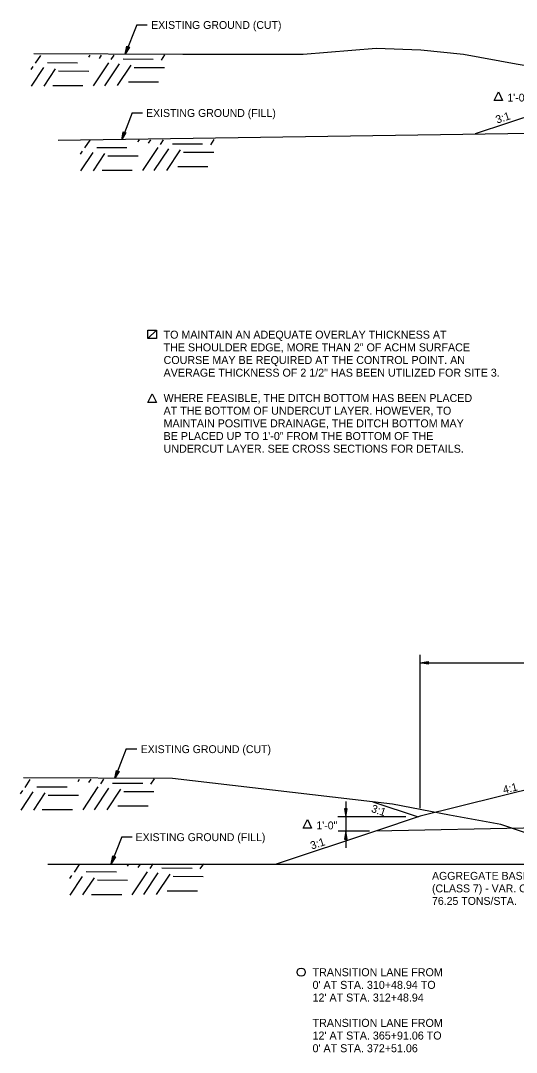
# Model space of a CAD drawing. Extents: x 1398565 to 1398920, y 1968324 to 1968581.
# Drawn here: x 1398764 to 1398801.2, y 1968479.9 to 1968557.3 of the extents above; entities that cross this region are included whole.
import ezdxf

# ---------------------------------------------------------------- set-up
doc = ezdxf.new("R2010")
doc.units = 0
for name, color, linetype in [('10', 7, 'Continuous'), ('19', 7, 'Continuous'), ('42', 7, 'Continuous'), ('9', 7, 'Continuous'), ('Default', 7, 'Continuous')]:
    doc.layers.add(name, color=color, linetype=linetype)

msp = doc.modelspace()

# ---------------------------------------------------------------- linework, layer by layer
at = {"layer": '10'}
for points in [[(1398799.825, 1968551.931), (1398800.145, 1968551.29), (1398799.504, 1968551.29)], [(1398773.545, 1968534.07), (1398774.186, 1968534.07), (1398774.186, 1968533.428), (1398773.545, 1968533.428)], [(1398773.545, 1968534.07), (1398774.186, 1968534.07), (1398773.545, 1968533.428)], [(1398773.865, 1968529.292), (1398774.186, 1968528.65), (1398773.545, 1968528.65)], [(1398785.503, 1968497.368), (1398785.823, 1968496.727), (1398785.182, 1968496.727)]]:
    msp.add_lwpolyline(points, close=True, dxfattribs=at)
msp.add_circle((1398785.033, 1968485.929), 0.306, dxfattribs=at)
at = {"layer": '19'}
for p, q in [((1398772.703, 1968556.959), (1398771.847, 1968554.758)), ((1398772.703, 1968556.959), (1398773.486, 1968556.959)), ((1398771.847, 1968554.758), (1398771.966, 1968555.355)), ((1398772.162, 1968555.279), (1398771.847, 1968554.758)), ((1398771.891, 1968554.912), (1398772.018, 1968555.335)), ((1398772.115, 1968555.297), (1398771.919, 1968554.901)), ((1398771.966, 1968555.355), (1398772.162, 1968555.279)), ((1398806.753, 1968551.672), (1398798.077, 1968548.78)), ((1398772.364, 1968550.361), (1398771.578, 1968548.342)), ((1398772.364, 1968550.361), (1398773.146, 1968550.361)), ((1398771.578, 1968548.342), (1398771.698, 1968548.939)), ((1398771.893, 1968548.863), (1398771.578, 1968548.342)), ((1398771.622, 1968548.496), (1398771.749, 1968548.919)), ((1398771.847, 1968548.881), (1398771.65, 1968548.485)), ((1398771.698, 1968548.939), (1398771.893, 1968548.863)), ((1398793.969, 1968498.237), (1398793.969, 1968509.724)), ((1398793.969, 1968509.124), (1398794.569, 1968509.229)), ((1398793.969, 1968509.124), (1398817.969, 1968509.124)), ((1398794.569, 1968509.019), (1398793.969, 1968509.124)), ((1398794.129, 1968509.139), (1398794.569, 1968509.174)), ((1398794.569, 1968509.069), (1398794.129, 1968509.109)), ((1398794.569, 1968509.229), (1398794.569, 1968509.019)), ((1398771.919, 1968502.667), (1398771.063, 1968500.465)), ((1398771.919, 1968502.667), (1398772.702, 1968502.667)), ((1398771.063, 1968500.465), (1398771.183, 1968501.062)), ((1398771.378, 1968500.986), (1398771.063, 1968500.465)), ((1398771.107, 1968500.62), (1398771.234, 1968501.042)), ((1398771.332, 1968501.004), (1398771.135, 1968500.609)), ((1398771.183, 1968501.062), (1398771.378, 1968500.986)), ((1398809.969, 1968501.621), (1398793.969, 1968497.621)), ((1398788.392, 1968498.729), (1398788.392, 1968497.454)), ((1398790.404, 1968498.711), (1398793.821, 1968497.572)), ((1398788.497, 1968498.172), (1398788.287, 1968498.172)), ((1398788.287, 1968498.172), (1398788.392, 1968497.572)), ((1398788.342, 1968498.172), (1398788.377, 1968497.732)), ((1398788.392, 1968497.572), (1398788.497, 1968498.172)), ((1398788.407, 1968497.732), (1398788.447, 1968498.172)), ((1398788.392, 1968497.454), (1398788.392, 1968495.248)), ((1398793.969, 1968497.621), (1398790.6, 1968496.498)), ((1398842.969, 1968497.545), (1398790.6, 1968496.498)), ((1398790.6, 1968496.498), (1398783.166, 1968494.02)), ((1398788.392, 1968496.498), (1398788.287, 1968495.898)), ((1398788.377, 1968496.338), (1398788.342, 1968495.898)), ((1398788.497, 1968495.898), (1398788.392, 1968496.498)), ((1398788.447, 1968495.898), (1398788.407, 1968496.338)), ((1398771.58, 1968496.069), (1398770.794, 1968494.049)), ((1398771.58, 1968496.069), (1398772.362, 1968496.069)), ((1398788.287, 1968495.898), (1398788.497, 1968495.898)), ((1398770.794, 1968494.049), (1398770.914, 1968494.646)), ((1398771.11, 1968494.57), (1398770.794, 1968494.049)), ((1398770.838, 1968494.204), (1398770.965, 1968494.626)), ((1398771.063, 1968494.588), (1398770.866, 1968494.193)), ((1398770.914, 1968494.646), (1398771.11, 1968494.57))]:
    msp.add_line(p, q, dxfattribs=at)
at = {"layer": '42'}
for points in [[(1398815.853, 1968549.872), (1398808.022, 1968552.85), (1398801.167, 1968554.018), (1398797.201, 1968554.737), (1398793.998, 1968555.048), (1398790.661, 1968555.193), (1398785.193, 1968554.732), (1398776.174, 1968554.74), (1398764.998, 1968554.785)], [(1398766.812, 1968548.312), (1398812.323, 1968548.993), (1398816.74, 1968550.093), (1398837.753, 1968555.327), (1398843.753, 1968555.567)], [(1398766.028, 1968494.02), (1398808.809, 1968494.02), (1398815.956, 1968495.8), (1398836.969, 1968501.034), (1398842.969, 1968501.274)], [(1398808.809, 1968494.02), (1398800.009, 1968497.014), (1398796.149, 1968497.696), (1398791.889, 1968498.539), (1398775.39, 1968500.448), (1398764.214, 1968500.493)]]:
    msp.add_lwpolyline(points, dxfattribs=at)
at = {"layer": '9'}
for p, q in [((1398765.122, 1968554.079), (1398765.51, 1968554.661)), ((1398769.105, 1968554.528), (1398769.208, 1968554.682)), ((1398769.903, 1968554.439), (1398770.068, 1968554.687)), ((1398770.794, 1968554.352), (1398771.021, 1968554.692)), ((1398771.683, 1968554.394), (1398773.945, 1968554.388)), ((1398774.557, 1968554.317), (1398774.822, 1968554.714)), ((1398764.784, 1968553.606), (1398764.938, 1968553.837)), ((1398764.812, 1968552.363), (1398765.735, 1968553.748)), ((1398765.765, 1968552.369), (1398766.626, 1968553.661)), ((1398766.011, 1968554.121), (1398768.273, 1968554.115)), ((1398766.849, 1968553.495), (1398769.111, 1968553.489)), ((1398769.463, 1968552.389), (1398770.61, 1968554.11)), ((1398770.323, 1968552.394), (1398771.407, 1968554.021)), ((1398771.275, 1968552.399), (1398772.298, 1968553.933)), ((1398772.521, 1968553.768), (1398774.783, 1968553.762)), ((1398766.41, 1968552.417), (1398768.672, 1968552.411)), ((1398772.082, 1968552.69), (1398774.344, 1968552.684)), ((1398768.817, 1968547.722), (1398769.205, 1968548.304)), ((1398772.801, 1968548.171), (1398772.904, 1968548.325)), ((1398773.598, 1968548.082), (1398773.763, 1968548.33)), ((1398774.489, 1968547.995), (1398774.716, 1968548.335)), ((1398778.253, 1968547.96), (1398778.517, 1968548.357)), ((1398768.479, 1968547.249), (1398768.633, 1968547.48)), ((1398768.507, 1968546.006), (1398769.431, 1968547.391)), ((1398769.46, 1968546.012), (1398770.321, 1968547.304)), ((1398769.707, 1968547.764), (1398771.969, 1968547.758)), ((1398773.158, 1968546.032), (1398774.305, 1968547.753)), ((1398774.018, 1968546.037), (1398775.103, 1968547.664)), ((1398774.97, 1968546.042), (1398775.993, 1968547.577)), ((1398775.379, 1968548.037), (1398777.64, 1968548.031)), ((1398776.216, 1968547.411), (1398778.478, 1968547.405)), ((1398770.544, 1968547.138), (1398772.806, 1968547.132)), ((1398770.105, 1968546.06), (1398772.367, 1968546.054)), ((1398775.777, 1968546.333), (1398778.039, 1968546.327)), ((1398764.338, 1968499.786), (1398764.726, 1968500.369)), ((1398768.321, 1968500.235), (1398768.424, 1968500.39)), ((1398769.119, 1968500.147), (1398769.284, 1968500.394)), ((1398770.01, 1968500.059), (1398770.237, 1968500.4)), ((1398773.774, 1968500.024), (1398774.038, 1968500.421)), ((1398764, 1968499.313), (1398764.154, 1968499.544)), ((1398764.028, 1968498.071), (1398764.952, 1968499.456)), ((1398764.981, 1968498.076), (1398765.842, 1968499.368)), ((1398765.227, 1968499.828), (1398767.489, 1968499.822)), ((1398768.679, 1968498.097), (1398769.826, 1968499.817)), ((1398769.539, 1968498.101), (1398770.623, 1968499.729)), ((1398770.491, 1968498.107), (1398771.514, 1968499.641)), ((1398770.899, 1968500.101), (1398773.161, 1968500.095)), ((1398771.737, 1968499.475), (1398773.999, 1968499.469)), ((1398766.065, 1968499.202), (1398768.327, 1968499.196)), ((1398765.626, 1968498.124), (1398767.888, 1968498.118)), ((1398771.298, 1968498.397), (1398773.56, 1968498.391)), ((1398768.033, 1968493.429), (1398768.421, 1968494.012)), ((1398772.017, 1968493.878), (1398772.12, 1968494.033)), ((1398772.815, 1968493.79), (1398772.98, 1968494.037)), ((1398773.705, 1968493.702), (1398773.932, 1968494.043)), ((1398777.469, 1968493.668), (1398777.733, 1968494.064)), ((1398767.695, 1968492.956), (1398767.849, 1968493.187)), ((1398768.923, 1968493.471), (1398771.185, 1968493.465)), ((1398772.374, 1968491.74), (1398773.521, 1968493.46)), ((1398773.234, 1968491.744), (1398774.319, 1968493.372)), ((1398774.186, 1968491.75), (1398775.209, 1968493.284)), ((1398774.595, 1968493.744), (1398776.857, 1968493.738)), ((1398767.723, 1968491.714), (1398768.647, 1968493.099)), ((1398768.676, 1968491.719), (1398769.537, 1968493.011)), ((1398769.761, 1968492.845), (1398772.023, 1968492.839)), ((1398775.432, 1968493.118), (1398777.694, 1968493.112)), ((1398769.322, 1968491.767), (1398771.584, 1968491.761)), ((1398774.993, 1968492.04), (1398777.255, 1968492.034))]:
    msp.add_line(p, q, dxfattribs=at)
at = {"layer": 'Default'}
for p, q in [((1398792.876, 1968497.572), (1398787.797, 1968497.572)), ((1398790.164, 1968496.498), (1398787.811, 1968496.498))]:
    msp.add_line(p, q, dxfattribs=at)

# ---------------------------------------------------------------- texts
at = {"layer": '10'}
for s, height, rotation, p in [('EXISTING GROUND (CUT)', 0.59001, 360, (1398773.787, 1968556.648)), ('1\'-0"', 0.59, 360, (1398800.499, 1968551.204)), ('EXISTING GROUND (FILL)', 0.59001, 360, (1398773.406, 1968550.05)), ('3:1', 0.59, 18.49392, (1398799.733, 1968549.542)), ('EXISTING GROUND (CUT)', 0.59001, 360, (1398773.003, 1968502.356)), ('4:1', 0.59, 13.73639, (1398800.242, 1968499.307)), ('3:1', 0.59, 341.52236, (1398790.238, 1968497.96)), ('1\'-0"', 0.59, 360, (1398786.177, 1968496.64)), ('EXISTING GROUND (FILL)', 0.59001, 360, (1398772.622, 1968495.758)), ('3:1', 0.59, 18.49392, (1398785.841, 1968495.119))]:
    msp.add_text(s, height=height, rotation=rotation, dxfattribs=at).set_placement(p)
at = {"layer": '19'}
for s, p in [('AGGREGATE BASE COURSE', (1398794.849, 1968492.859)), ('(CLASS 7) - VAR. COMPACTED DEPTH', (1398794.849, 1968491.919)), ('76.25 TONS/STA.', (1398794.849, 1968490.979))]:
    msp.add_text(s, height=0.59001, rotation=360, dxfattribs=at).set_placement(p)
at = {"layer": '42'}
for s, p in [('TO MAINTAIN AN ADEQUATE OVERLAY THICKNESS AT', (1398774.72, 1968533.427)), ('THE SHOULDER EDGE, MORE THAN 2" OF ACHM SURFACE', (1398774.72, 1968532.477)), ('COURSE MAY BE REQUIRED AT THE CONTROL POINT. AN', (1398774.72, 1968531.527)), ('AVERAGE THICKNESS OF 2 1/2" HAS BEEN UTILIZED FOR SITE 3.', (1398774.72, 1968530.577)), ('WHERE FEASIBLE, THE DITCH BOTTOM HAS BEEN PLACED', (1398774.72, 1968528.677)), ('AT THE BOTTOM OF UNDERCUT LAYER. HOWEVER, TO', (1398774.72, 1968527.727)), ('MAINTAIN POSITIVE DRAINAGE, THE DITCH BOTTOM MAY', (1398774.72, 1968526.777)), ('BE PLACED UP TO 1\'-0" FROM THE BOTTOM OF THE', (1398774.72, 1968525.827)), ('UNDERCUT LAYER. SEE CROSS SECTIONS FOR DETAILS.', (1398774.72, 1968524.877)), ('TRANSITION LANE FROM', (1398785.891, 1968485.629)), ("0' AT STA. 310+48.94 TO", (1398785.891, 1968484.679)), ("12' AT STA. 312+48.94", (1398785.891, 1968483.729)), ('TRANSITION LANE FROM', (1398785.891, 1968481.829)), ("12' AT STA. 365+91.06 TO", (1398785.891, 1968480.879)), ("0' AT STA. 372+51.06", (1398785.891, 1968479.929))]:
    msp.add_text(s, height=0.6, dxfattribs=at).set_placement(p)

doc.saveas('drawing.dxf')
